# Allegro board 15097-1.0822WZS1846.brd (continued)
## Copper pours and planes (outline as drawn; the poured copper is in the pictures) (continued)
V_3P3_LAN on L3: 39.91,20.78 38.36,20.78 33.87,16.28 33.87,14.66 33.28,14.07 32.24,14.07 31.61,13.44 31.61,9.73 32.9,8.43 40.01,8.43 41.1,9.53 41.1,10.92 40.37,11.66 38.41,11.66 37.88,11.13 34.09,11.13 33.99,11.23 33.99,11.58 35.33,12.92 35.33,15.56 37.55,17.78 38.54,17.78 40.14,19.38 40.14,20.55
V_3P3_PCIVAUX on TOP: 117.56,222.33 117.48,222.4 117.48,222.63 117.51,222.66 119.34,222.66 119.36,222.68 119.36,222.86 117.51,222.86 117.48,222.88 117.48,224.26 117.71,224.49 121.72,224.49 121.9,224.3 121.9,223.62 122.14,223.39 122.14,222.55 121.91,222.33 ; 1 cut-out
V_3P3_PCIVAUX on TOP: 120.91,203.28 119.92,204.27 117.8,204.27 117.49,204.57 117.49,205.16 119.39,205.16 119.41,205.18 119.41,205.31 119.36,205.36 117.56,205.36 117.51,205.41 117.51,205.66 123.16,205.66 123.33,205.49 123.33,203.45 123.31,203.43 123.31,203.39 123.21,203.28 ; 4 cut-outs
V_3P3_PCIVAUX on BOTTOM: 119.54,202.82 115.48,206.88 115.48,221.75 117.13,223.4 117.13,224.54 117.51,224.92 121.39,224.92 121.63,224.68 121.63,223.02 121.41,222.8 119.46,222.8 117.97,221.32 117.97,207.94 119.79,206.12 124.62,206.12 126.02,207.52 126.02,209.04 126.65,209.68 130.59,209.68 130.84,209.42 130.84,203.2 130.46,202.82
V_5HDD on TOP: 10.8,193.37 10.02,194.16 10.02,201.14 10.45,201.57 13.09,201.57 13.83,200.84 13.83,200.25 15.4,198.68 20.25,198.68 20.31,198.62 20.31,195.92 20.3,195.91 20.3,193.5 20.18,193.37 ; 4 cut-outs
V_5HDD on BOTTOM: 16.91,193.8 16.68,194.03 16.67,194.03 16.67,196.47 17.05,196.85 20.1,196.85 20.35,196.6 20.35,193.8
V_5P0_HDMI_CONN on TOP: 115.5,40.55 115.38,40.67 115.38,40.98 115.38,40.99 115.38,41.33 115.53,41.48 118.37,41.48 118.4,41.44 118.4,41.19 118.36,41.15 116.38,41.15 115.78,40.55
V_5P0_HDMI_CONN on BOTTOM: 117.84,37.92 115.22,40.54 115.22,40.97 115.5,41.25 116.01,41.25 117.89,39.37 120.43,39.37 120.53,39.27 120.53,38.13 120.33,37.92 ; 2 cut-outs
V_5P0_HDMI_CONN_L on BOTTOM: 117.91,34.55 117.73,34.72 117.73,37.09 118.04,37.39 120.45,37.39 120.56,37.29 120.56,34.65 120.48,34.57 118.93,34.57 118.91,34.55
V_19_INV on TOP: 37.65,33.91 35.85,35.71 35.85,42.03 35.85,42.03 35.85,43.82 36.28,44.25 40.9,44.25 41.82,43.33 41.82,34.8 40.93,33.91
VOUT_INV on TOP: 25.55,37.6 25.36,37.8 25.36,39.67 25.56,39.88 26.96,39.88 27.34,39.5 28.99,39.5 29.12,39.37 29.12,37.97 28.99,37.85 27.19,37.85 26.94,37.6
VOUT_INV on BOTTOM: 28.89,33.99 28.48,34.39 28.48,35.18 27.85,35.81 23.27,35.81 22.89,36.2 22.89,39.62 23.4,40.13 28.23,40.13 28.61,39.75 28.61,38.4 29.01,38 31.25,38 31.34,37.91 31.34,36.31 30.82,35.79 30.82,34.37 30.44,33.99

Small or netless copper shapes (teardrops, artwork), in the pictures only: 5 on TOP, 5 on BOTTOM

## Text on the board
Ref Des/Silkscreen Bottom: F8:1.5A/6V | F3:1.5A/6V | F4:1.5A/6V | F7:1.5A/6V | F5:1.5A/6V
Ref Des/Silkscreen Top: SERVICE_MODE | 5-6 SHORT:ME DISABLE | 5-6 OPEN:DEFAULT | 3-4 SHORT:DEFAULT | PASSWORD | JMP1 | 3-4 OPEN:PASSWOAD RESET | 1-2 SHORT:RTC_CMOS RESET | RTC_CMOS | 1-2 OPEN:DEFAULT | F1:2A/6V | X4:25MHZ | PPID | JO1230 | X2:19.2MHZ | A1 | A63 | X3:27MHZ | BJ1 | Rev:A00 | Dell:5DWRY | 3 | 5 | 1 | 6 | 4 | 2 | F2:3A/32V | X1:32.768KHZ | BJ63 | Apollo-Lake AiO | 15097-1 | 5DWRY | MADE IN TAIWAN | M2
User.23: 132 | 230 | 75 | 0 | n | 4.5 (Screw hole) | 8(PTH) | 5 | 7.5 (NO COMPONENT) | 5- | 2.7 (PTH) | 4 (PTH) | 6 (PTH) | 9.5 | 2- | 8(NPTH) | 6.5 (PTH) | 4.5 | 4.5(Screw hole) | 162.4 | 66.9 | 3.5(Screw hole) | 59.9 | 15 | 30 | 38 | 165 | 195 | Hight Limitation TOP VIEW
User.24: White LIne mark | White line mark | OPEN SOLDERMASK | Hight Limitation BOTTOM VIEW
User.26: GND | 1V_CPU_VCGI | AGND | 1V_CPU_VNN
User.27: Board Accuracy Check,Aug 22 18:17:58 2016,Passed | Dummy-Static-No Shape On Layer Check,Aug 22 18:17:58 2016,Passed | Split Plane Check,Aug 22 18:17:57 2016,Passed | Via Check,Mar 10 15:11:23 2016,233 errors
User.29: ByImpedance:100.0@_REF_L1=("3.5/10.0(L1)")|_REF_L6=("3.5/10.0(L6)")|Type="DP"|_REF_L4=("4.0/9.0(L4)")|_REF_L3=("4.0/9.0(L3)")|imp="100.0" | ByImpedance:110.0@Type="DP"|_REF_L4=("3.5/13.0(L4)")|_REF_L3=("3.5/13.0(L3)")|imp="110.0" | ByImpedance:27.4@_REF_L1=("12.0(L1)")|_REF_L6=("12.0(L6)")|Type="SE"|_REF_L4=("16.0(L4)")|_REF_L3=("16.0(L3)")|imp="27.4" | ByImpedance:33.0@_REF_L1=("9.0(L1)")|_REF_L6=("9.0(L6)")|Type="SE"|_REF_L4=("12.0(L4)")|_REF_L3=("12.0(L3)")|imp="33.0" | ByImpedance:34.0@_REF_L1=("8.5(L1)")|_REF_L6=("8.5(L6)")|Type="SE"|_REF_L4=("11.5(L4)")|_REF_L3=("11.5(L3)")|imp="34.0" | ByImpedance:35.0@_REF_L1=("8.0(L1)")|_REF_L6=("8.0(L6)")|Type="SE"|_REF_L4=("10.5(L4)")|_REF_L3=("10.5(L3)")|imp="35.0" | ByImpedance:37.5@_REF_L1=("7.0(L1)")|_REF_L6=("7.0(L6)")|Type="SE"|_REF_L4=("9.5(L4)")|_REF_L3=("9.5(L3)")|imp="37.5" | ByImpedance:39.0@_REF_L1=("6.5(L1)")|_REF_L6=("6.5(L6)")|Type="SE"|_REF_L4=("9.0(L4)")|_REF_L3=("9.0(L3)")|imp="39.0" | ByImpedance:40.0@_REF_L1=("6.5(L1)")|_REF_L6=("6.5(L6)")|Type="SE"|_REF_L4=("8.5(L4)")|_REF_L3=("8.5(L3)")|imp="40.0" | ByImpedance:42.0@_REF_L1=("5.5(L1)")|_REF_L6=("5.5(L6)")|Type="SE"|_REF_L4=("7.5(L4)")|_REF_L3=("7.5(L3)")|imp="42.0" | ByImpedance:45.0@_REF_L1=("5.0(L1)")|_REF_L6=("5.0(L6)")|Type="SE"|_REF_L4=("6.5(L4)")|_REF_L3=("6.5(L3)")|imp="45.0" | ByImpedance:48.0@_REF_L1=("4.5(L1)")|_REF_L6=("4.5(L6)")|Type="SE"|_REF_L4=("5.5(L4)")|_REF_L3=("5.5(L3)")|imp="48.0" | ByImpedance:50.0@_REF_L1=("4.0(L1)")|_REF_L6=("4.0(L6)")|Type="SE"|_REF_L4=("5.0(L4)")|_REF_L3=("5.0(L3)")|imp="50.0" | ByImpedance:52.0@_REF_L1=("3.5(L1)")|_REF_L6=("3.5(L6)")|Type="SE"|_REF_L4=("4.5(L4)")|_REF_L3=("4.5(L3)")|imp="52.0" | ByImpedance:55.0@Type="SE"|_REF_L4=("4.0(L4)")|_REF_L3=("4.0(L3)")|imp="55.0" | ByImpedance:65.0@_REF_L1=("8.0/6.0(L1)")|_REF_L6=("8.0/6.0(L6)")|Type="DP"|_REF_L4=("9.0/5.0(L4)")|_REF_L3=("9.0/5.0(L3)")|imp="65.0" | ByImpedance:68.0@_REF_L1=("6.5/4.0(L1)")|_REF_L6=("6.5/4.0(L6)")|Type="DP"|_REF_L4=("7.5/4.0(L4)")|_REF_L3=("7.5/4.0(L3)")|imp="68.0" | ByImpedance:70.0@_REF_L1=("7.0/6.0(L1)")|_REF_L6=("7.0/6.0(L6)")|Type="DP"|_REF_L4=("8.0/6.0(L4)")|_REF_L3=("8.0/6.0(L3)")|imp="70.0" | ByImpedance:72.0@_REF_L1=("7.0/8.0(L1)")|_REF_L6=("7.0/8.0(L6)")|Type="DP"|_REF_L4=("7.0/5.0(L4)")|_REF_L3=("7.0/5.0(L3)")|imp="72.0" | ByImpedance:75.0@_REF_L1=("6.0/6.0(L1)")|_REF_L6=("6.0/6.0(L6)")|Type="DP"|_REF_L4=("7.0/6.0(L4)")|_REF_L3=("7.0/6.0(L3)")|imp="75.0" | ByImpedance:80.0@_REF_L1=("5.0/5.0(L1)")|_REF_L6=("5.0/5.0(L6)")|Type="DP"|_REF_L4=("6.0/6.0(L4)")|_REF_L3=("6.0/6.0(L3)")|imp="80.0" | ByImpedance:85.0@_REF_L1=("5.0/8.0(L1)" "4.0/4.5(L1)")|_REF_L6=("5.0/8.0(L6)" "4.0/4.5(L6)")|Type="DP"|_REF_L4=("5.0/5.5(L4)")|_REF_L3=("5.0/5.5(L3)")|imp="85.0" | ByImpedance:90.0@_REF_L1=("4.0/6.0(L1)")|_REF_L6=("4.0/6.0(L6)")|Type="DP"|_REF_L4=("5.0/8.0(L4)" "4.0/5.0(L4)")|_REF_L3=("5.0/8.0(L3)" "4.0/5.0(L3)")|imp="90.0" | ByImpedance:93.0@_REF_L1=("4.0/8.0(L1)" "3.5/5.5(L1)")|_REF_L6=("4.0/8.0(L6)" "3.5/5.5(L6)")|Type="DP"|_REF_L4=("5.0/9.0(L4)" "4.0/5.5(L4)")|_REF_L3=("5.0/9.0(L3)" "4.0/5.5(L3)")|imp="93.0" | ByImpedance:95.0@_REF_L1=("4.0/10.0(L1)" "3.5/6.0(L1)")|_REF_L6=("4.0/10.0(L6)" "3.5/6.0(L6)")|Type="DP"|_REF_L4=("4.0/6.5(L4)")|_REF_L3=("4.0/6.5(L3)")|imp="95.0" | LayerIndex:nil | Source:6-1.2-7c.xls | artWorks:("_REF_L3" "_REF_L4" "_REF_L6" "_REF_L1") | gtImpOutlineUsed:BOARD GEOMETRY/PANEL_OUTLINE
User.30: GND | AGND
User.45: Note:Refer to DRILL layer for ELLIPSE drill direction | FIGURE | SIZE | 10.0 | 12.0 | 16.0 | 20.0 | 28.0 | 30.0 | 36.0 | 37.0 | 39.0 | 40.0 | 60.0 | 91.0 | 109.0 | 158.0 | 42.0 | 44.0 | 50.0 | 54.0 | 63.0 | 67.0 | 86.0 | 134.0 | 138.0 | 178.0 | 48.0x16.0 | 56.0x24.0 | 60.0x24.0 | 60.0x28.0 | 67.0x28.0 | 67.0x30.0 | 67.0x32.0 | 91.0x28.0 | 156.0x32.0 | 166.0x32.0 | 197.0x178.0 | DRILL CHART: TOP to BOTTOM | ALL UNITS ARE IN MILS | PLATED | NON-PLATED | QTY | 1656 | 1796 | 958 | 40 | 18 | 14 | 8 | 15 | 4 | 1 | 5 | 3 | 2 | This gerber is just for your reference to find the DP impedance traces in layer L1. | This gerber is just for your reference to find the DP impedance traces in layer L3. | This gerber is just for your reference to find the DP impedance traces in layer L4. | This gerber is just for your reference to find the DP impedance traces in layer L6. | This gerber is just for your reference to find the SE impedance traces in layer L1. | This gerber is just for your reference to find the SE impedance traces in layer L3. | This gerber is just for your reference to find the SE impedance traces in layer L4. | This gerber is just for your reference to find the SE impedance traces in layer L6. | DP IMPEDANCE TABLE: L1 | DP IMPEDANCE TABLE: L3 | DP IMPEDANCE TABLE: L4 | DP IMPEDANCE TABLE: L6 | SE IMPEDANCE TABLE: L1 | SE IMPEDANCE TABLE: L3 | SE IMPEDANCE TABLE: L4 | SE IMPEDANCE TABLE: L6 | * - Denotes that WIDTH | is NOT used in this layer | inside board outline. | Model | Apollo-Lake AiO | ECO_NO | 878940 | PCB_NO | 15097 | VER. | Layer | DRILL | L1 | L2VCC | L3 | TMASK | TPLACE | TSILK | TSMD | Designer | MOSSE | Date | 08/23/2016 | IMP(Ohm) | 27.4 | 65.0 | 33.0 | 68.0 | 34.0 | 70.0 | 35.0 | 72.0 | 37.5 | 75.0 | 80.0 | 85.0 | 90.0 | 45.0 | 48.0 | 93.0 | 52.0 | 95.0 | 100.0 | 55.0 | 110.0 | WIDTH(mils) | *16.0 | *9.0 | 9.0 | *11.5 | *8.5 | *10.5 | 8.0 | *9.5 | 7.0 | 6.5 | 5.5 | 7.5 | 5.0 | *4.5 | *5.5 | 4.0 | 3.5 | 4.5 | *8.0/6.0 | *9.0/5.0 | *6.5/4.0 | *7.5/4.0 | *7.0/6.0 | *7.0/5.0 | *7.0/8.0 | *6.0/6.0 | 5.0/5.0 | 6.0/6.0 | *5.0/8.0 | 5.0/5.5 | 4.0/4.5 | *4.0/5.0 | 4.0/6.0 | *5.0/9.0 | 4.0/8.0 | *3.5/5.5 | *4.0/5.5 | *4.0/6.5 | 4.0/10.0 | *3.5/6.0 | 4.0/9.0 | *3.5/13.0 | 3.5/10.0 | TYPE | SE | DP | BMASK | BPLACE | BSILK | BSMD | L4 | L5GND | L6
